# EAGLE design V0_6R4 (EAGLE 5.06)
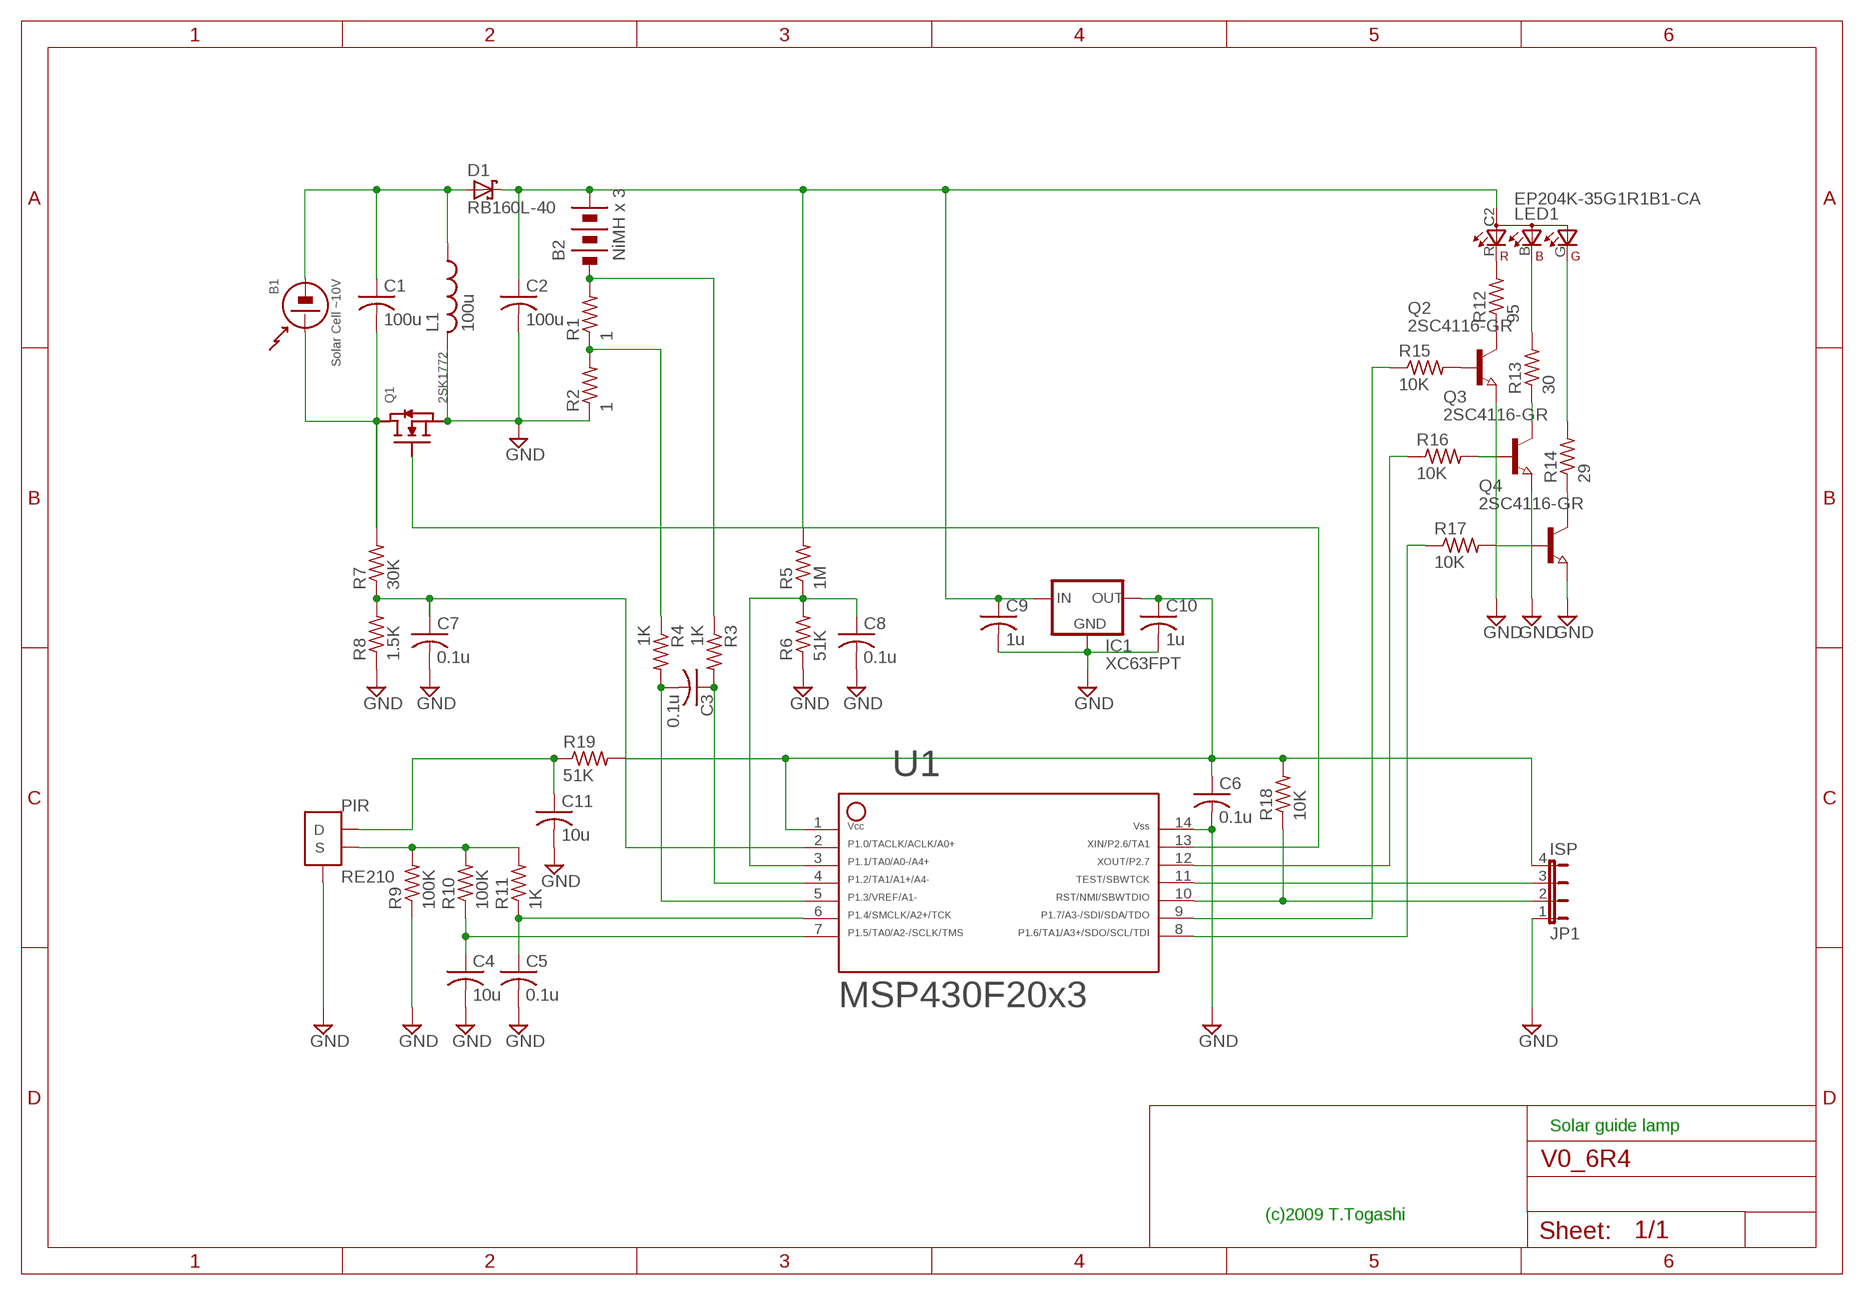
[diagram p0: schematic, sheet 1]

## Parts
B1  Solar Cell ~10V  SOLARCELL  [CONN-2P]
B2  NiMH x 3  BATTERY-3  [CONN-2P]
C1  100u  C-USC3216  [C3216]
C2  100u  C-USC3216  [C3216]
C3  0.1u  C-USC1608  [C1608]
C4  10u  C-USC3216  [C3216]
C5  0.1u  C-USC1608  [C1608]
C6  0.1u  C-USC1608  [C1608]
C7  0.1u  C-USC1608  [C1608]
C8  0.1u  C-USC1608  [C1608]
C9  1u  C-USC3216  [C3216]
C10  1u  C-USC3216  [C3216]
C11  10u  C-USC3216  [C3216]
D1  RB160L-40  SCHOTTKY-DIODESMD  [SMB]
IC1  XC63FPT  [TO92]
JP1  ISP  JP4E  [JP4]
L1  100u  L-USL5650M  [L5650M]
LED1  EP204K-35G1R1B1-CA  [EP204K]
PIR  RE210  [TO-5]
Q1  2SK1772  [UPAK-RENESAS]
Q2  2SC4116-GR  NPN-TRANSISTOR_SOT23  [SOT23]
Q3  2SC4116-GR  NPN-TRANSISTOR_SOT23  [SOT23]
Q4  2SC4116-GR  NPN-TRANSISTOR_SOT23  [SOT23]
R1  1  R-US_M2012  [M2012]
R2  1  R-US_M2012  [M2012]
R3  1K  R-US_R0603  [R0603]
R4  1K  R-US_R0603  [R0603]
R5  1M  R-US_R0603  [R0603]
R6  51K  R-US_R0603  [R0603]
R7  30K  R-US_R0603  [R0603]
R8  1.5K  R-US_R0603  [R0603]
R9  100K  R-US_R0603  [R0603]
R10  100K  R-US_R0603  [R0603]
R11  1K  R-US_R0603  [R0603]
R12  95  R-US_R0603  [R0603]
R13  30  R-US_R0603  [R0603]
R14  29  R-US_R0603  [R0603]
R15  10K  R-US_R0603  [R0603]
R16  10K  R-US_R0603  [R0603]
R17  10K  R-US_R0603  [R0603]
R18  10K  R-US_R0603  [R0603]
R19  51K  R-US_R0603  [R0603]
U1  F2013  F20X3---N14  [N14]

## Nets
ETM250-1.5V: B1.P$2(MINUS) C1.1 D1.A L1.1
GND: C2.2 C4.2 C5.2 C6.2 C7.2 C8.2 C9.2 C10.2 C11.2 IC1.1(GND) JP1.1 L1.2 PIR.3(GND) Q1.3(S) Q2.2(E) Q3.2(E) Q4.2(E) R2.1 R6.1 R8.1 R9.1 U1.14
N$1: B2.P$2(MINUS) R1.2 R3.1
N$2: R1.1 R2.2 R4.1
N$3: C3.2 R4.2 U1.5
N$4: B2.P$1(PLUS) C2.1 C9.1 D1.C IC1.2(IN) LED1.C2(A1) LED1.C(A2) R5.2
N$5: R17.1 U1.8
N$6: C8.1 R5.1 R6.2 U1.3
N$7: C3.1 R3.2 U1.4
N$8: C7.1 R7.1 R8.2 U1.2
N$9: Q1.1(G) U1.13
N$10: C4.1 R10.1 U1.7
N$12: PIR.2(S) R9.2 R10.2 R11.2
N$13: C6.1 C10.1 IC1.3(OUT) JP1.4 R18.2 R19.2 U1.1
N$14: LED1.R(CRED) R12.2
N$15: Q2.3(C) R12.1
N$16: LED1.B(CBLUE) R13.2
N$17: LED1.G(CGREEN) R14.2
N$18: Q2.1(B) R15.2
N$19: Q3.1(B) R16.2
N$20: Q4.1(B) R17.2
N$21: Q3.3(C) R13.1
N$22: Q4.3(C) R14.1
N$23: R15.1 U1.9
N$24: R16.1 U1.12
N$25: C5.1 R11.1 U1.6
N$26: B1.P$1(PLUS) C1.2 Q1.2(D) R7.2
N$29: JP1.2 R18.1 U1.10
N$30: JP1.3 U1.11
N$31: C11.1 PIR.1(D) R19.1

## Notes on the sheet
- Solar guide lamp
- (c)2009 T.Togashi

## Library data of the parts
B1 = TOG:SOLARCELL: Solar cell
B2 = TOG:BATTERY-3: Battery 3cell
C1-C11 = rcl:C-US: CAPACITOR, American symbol
D1 = diode:SCHOTTKY-DIODE: Schottky Diode
IC1 = v-reg:XC63FP: Positiv Voltage Regulators www.torex.co.jp/english/product/pro02/pdf/0201_xc62fp.pdf
JP1 = jumper:JP4E: JUMPER
L1 = rcl:L-US: INDUCTOR, American symbol
LED1 = led:EP204K-35G1R1B1-CA
PIR = TOG:RE210
Q1 = TOG:2SK1772: N-ch MOS FET
Q2-Q4 = semicon-smd-ipc:NPN-TRANSISTOR_: NPN TRANSISTOR
R1-R19 = rcl:R-US_: RESISTOR, American symbol
U1 = TI_MSP430_v13:F20X3---N14: ***MSP430F20x3***N14

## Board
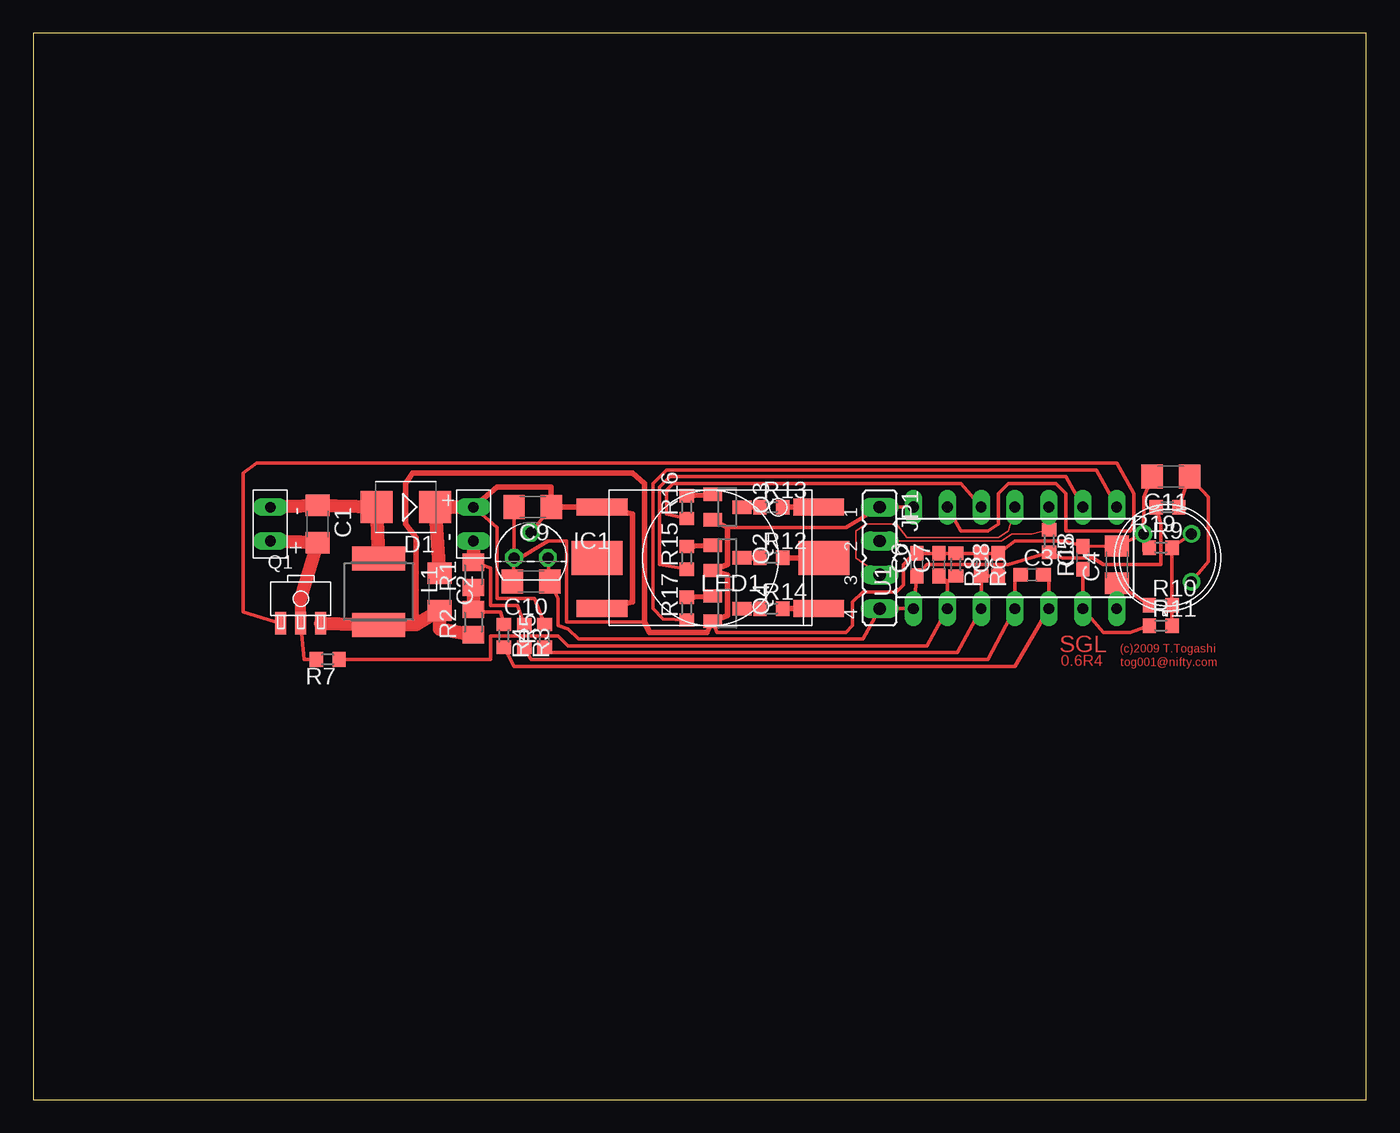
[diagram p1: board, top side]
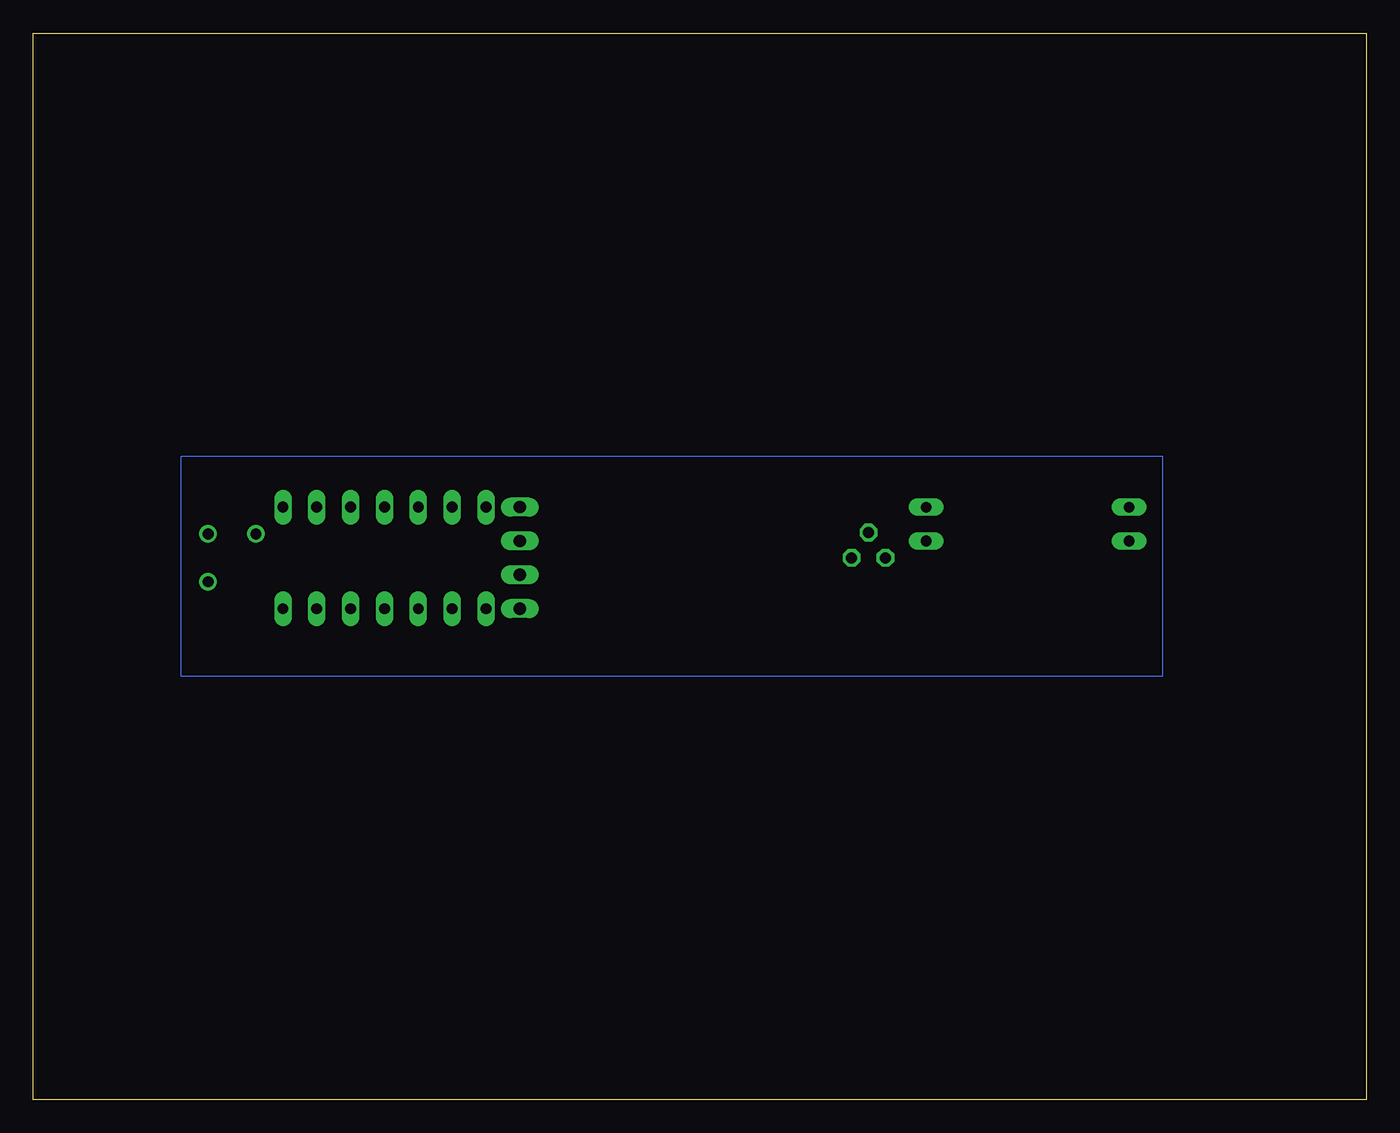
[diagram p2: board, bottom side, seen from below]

Size 100 x 80 mm. Coordinates in mm from the lower left corner, seen from the top.
Outline: 0,0 100,0 100,80 0,80 0,0
Copper layers (1*16): Top 0.035mm / dielectric 1.5mm / Bottom 0.035mm
Design rules "default": minimum track width 10mil, minimum drill 24mil, track to track 8mil, track to pad 8mil, pad to pad 8mil, via to via 8mil, smd to smd 8mil, copper to edge 40mil, drill to drill 8mil, minimum pad ring 10mil, minimum via ring 8mil, stop-mask expansion 4mil, vias tented up to drill 0mil, thermal gap 10mil

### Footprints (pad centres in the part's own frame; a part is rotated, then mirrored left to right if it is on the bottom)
CONN-2P = drill 0.8 long: P$1 1.27,0; P$2 -1.27,0
C3216 = smd 1.6 x 1.8: 1 -1.4,0; 2 1.4,0
C1608 = smd 1.1 x 1: 1 -0.85,0; 2 0.85,0
SMB = smd 2.4 x 2.4: A 2.2,0; C -2.2,0
TO92 = drill 0.813 octagon: 1 -1.27,0; 2 0,1.905; 3 1.27,0
JP4 = drill 0.914 long: 1 -3.81,0; 2 -1.27,0; 3 1.27,0; 4 3.81,0
L5650M = smd 1.8 x 4: 1 -2.5,0; 2 2.5,0
EP204K = smd 1.27 x 3.81: B 3.81,-8.128; C -3.81,8.128; C2 3.81,8.128; G -3.81,-8.128 | smd 2.54 x 3.81: R 0,-8.509; R2 0,8.509
TO-5 = drill 0.8 round: 1 0,-2.54; 2 2.54,0; 3 0,2.54
UPAK-RENESAS = smd 0.813 x 1.676: 1 -1.5,-1.1; 2 0,-1.1; 3 1.5,-1.1
SOT23 = smd 1 x 1.4: 1 -0.95,-1.1; 2 0.95,-1.1; 3 0,1.1
M2012 = smd 1.3 x 1.6: 1 -0.95,0; 2 0.95,0
R0603 = smd 1 x 1.1: 1 -0.85,0; 2 0.85,0
N14 = drill 0.813 long: 1 -7.625,-3.81; 2 -5.085,-3.81; 3 -2.545,-3.81; 4 -0.005,-3.81; 5 2.535,-3.81; 6 5.075,-3.81; 7 7.615,-3.81; 8 7.615,3.81; 9 5.075,3.81; 10 2.535,3.81; 11 -0.005,3.81; 12 -2.545,3.81; 13 -5.085,3.81; 14 -7.625,3.81

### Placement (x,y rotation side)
B1  17.78,43.18 270 top
B2  33.02,43.18 90 top
C1  21.34,43.18 270 top
C2  30.48,38.1 270 top
C3  74.93,39.37 0 top
C4  81.28,40.13 90 top
C5  78.74,40.64 90 top
C6  66.29,40.13 90 top
C7  67.94,40.13 90 top
C8  72.39,40.13 90 top
C9  37.47,44.45 180 top
C10  37.34,38.86 180 top
C11  85.34,46.74 180 top
D1  27.94,44.45 180 top
IC1  37.34,40.64 0 top
JP1  63.5,40.64 270 top
L1  25.91,38.1 270 top
LED1  50.8,40.64 90 top
PIR  85.09,40.64 45 top
Q1  20.07,36.83 0 top
Q2  52.07,40.64 270 top
Q3  52.07,44.45 270 top
Q4  52.07,36.83 270 top
R1  33.02,39.37 90 top
R2  33.02,35.81 90 top
R3  36.83,34.8 270 top
R4  35.31,34.8 270 top
R5  38.35,34.8 90 top
R6  71.12,40.13 270 top
R7  22.1,33.02 180 top
R8  69.22,40.13 270 top
R9  84.58,41.4 0 top
R10  84.58,37.08 0 top
R11  84.58,35.56 0 top
R12  55.37,40.64 0 top
R13  55.37,44.45 0 top
R14  55.37,36.83 0 top
R15  49.02,40.64 90 top
R16  49.02,44.45 90 top
R17  49.02,36.83 90 top
R18  76.2,41.91 270 top
R19  85.09,44.45 180 top
U1  73.66,40.64 0 top

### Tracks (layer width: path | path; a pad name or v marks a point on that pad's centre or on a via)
ETM250-1.5V
  Top 1.016: B1.P$2 C1.1 D1.A L1.1
GND
  Top 0.254: JP1.1 U1.14 JP1.1 | C9.2 IC1.1 C10.2 36.07,40.39 38.61,41.91 40.01,41.91 40.01,35.81 45.85,35.81 | PIR.3 C4.2 C5.2 77.47,41.91 73.66,41.91 C8.2 R6.1 R8.1 C7.2 C6.2 66.03,40.98 65.28,40.13 65.28,38.61 64.77,38.1 62.23,38.1 61.47,37.34 61.47,35.56 60.96,35.05 51.31,35.05 Q4.2 | R9.1 83.31,41.15 83.31,41.4 PIR.3 | PIR.3 83.31,45.21 C11.2 | JP1.1 60.96,42.93 52.07,42.93
  Top 0.406: 28.71,35.65 28.7,42.16 27.94,43.18 27.94,46.23 28.45,46.99 44.96,46.99 45.85,46.23 45.85,35.81 46.23,35.05 50.55,35.05 Q4.2 52.07,36.32 52.07,39.37 Q2.2 52.07,40.13 52.07,42.93 Q3.2
  Top 1.016: R2.1 30.48,35.31 C2.2 28.71,35.65 L1.2 Q1.3
N$1
  Top 0.254: R3.1 36.32,37.08 34.29,37.08 34.29,39.88 R1.2
  Top 1.016: R1.2 B2.P$2
N$2
  Top 0.254: R4.1 35.05,36.58 33.53,36.58 R2.2
  Top 1.016: R2.2 R1.1
N$3
  Top 0.254: C3.2 76.2,39.37 U1.5 73.66,32.51 36.07,32.51 R4.2
N$4
  Top 0.254: R5.2 37.59,37.59 34.8,37.59 34.8,42.93 B2.P$1 | C9.1 IC1.2
  Top 0.406: LED1.C 44.96,37.34 44.96,43.94 LED1.C2 C9.1 38.86,45.97 34.8,45.97 B2.P$1
  Top 1.016: C2.1 D1.C B2.P$1
N$5
  Top 0.254: R17.1 47.24,36.07 46.48,36.83 46.48,46.23 47.5,47.24 79.76,47.24 U1.8
N$6
  Top 0.254: R6.2 U1.3 69.34,33.53 38.61,33.53 R5.1 | R6.2 C8.1
  Top 0.406: R6.2
N$7
  Top 0.254: C3.1 73.66,39.37 U1.4 71.63,33.02 37.34,33.02 R3.2
N$8
  Top 0.254: 68.58,38.86 U1.2 67.06,34.04 40.13,34.04 39.37,34.8 34.29,34.8 34.29,33.02 R7.1 | 68.58,38.86 R8.2 | 68.58,38.86 C7.1
N$9
  Top 0.254: U1.13 69.6,42.67 71.63,42.67 72.39,43.18 72.39,45.47 73.15,46.23 76.71,46.23 77.47,45.47 77.47,42.67 82.3,42.67 82.55,43.43 82.55,45.47 81.28,47.75 16.76,47.75 15.75,46.99 15.75,36.58 Q1.1
N$10
  Top 0.254: U1.7 C4.1 R10.1
N$12
  Top 0.254: R11.2 R10.2 R9.2 PIR.2
N$13
  Top 0.254: IC1.3 C10.1 39.37,37.59 39.37,35.56 40.13,35.31 40.89,34.54 62.23,34.54 JP1.4 U1.1 C6.1 67.06,40.13 73.15,40.13 R18.2 77.22,40.64 79.5,40.64 80.26,40.13 84.58,40.13 84.58,43.18 R19.2
N$14
  Top 0.406: R12.2 LED1.R
N$15
  Top 0.406: Q2.3 R12.1
N$16
  Top 0.406: R13.2 LED1.B
N$17
  Top 0.406: R14.2 LED1.G
N$18
  Top 0.406: R15.2 Q2.1
N$19
  Top 0.406: R16.2 Q3.1
N$20
  Top 0.406: R17.2 Q4.1
N$21
  Top 0.406: Q3.3 R13.1
N$22
  Top 0.406: Q4.3 R14.1
N$23
  Top 0.254: R15.1 46.99,40.13 46.99,45.97 47.75,46.74 77.47,46.74 U1.9
N$24
  Top 0.254: R16.1 47.5,43.94 47.5,45.72 48.01,46.23 69.6,46.23 U1.12
N$25
  Top 0.254: C5.1 U1.6 80.26,35.05 82.3,35.05 R11.1
N$26
  Top 0.254: R7.2 20.32,33.02 Q1.2
  Top 0.813: Q1.2 20.07,37.59
  Top 1.016: 20.07,37.59 C1.2 B1.P$1
N$27
  Bottom 0.051: 88.9,31.75 88.9,48.26 15.24,48.26 15.24,31.75 88.9,31.75
N$29
  Top 0.127: R18.1 74.93,42.42 73.41,42.42 72.64,41.91 JP1.2
  Top 0.254: R18.1 U1.10
N$30
  Top 0.127: U1.11 73.15,42.67 72.39,42.16 65.53,42.16 64.77,43.18 62.48,43.18 61.72,42.67 61.72,40.64 JP1.3
N$31
  Top 0.254: PIR.1 88.14,40.39 88.14,45.21 C11.1 R19.1

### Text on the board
Top: SGL | (c)2009 T.Togashi | 0.6R4 | tog001@nifty.com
